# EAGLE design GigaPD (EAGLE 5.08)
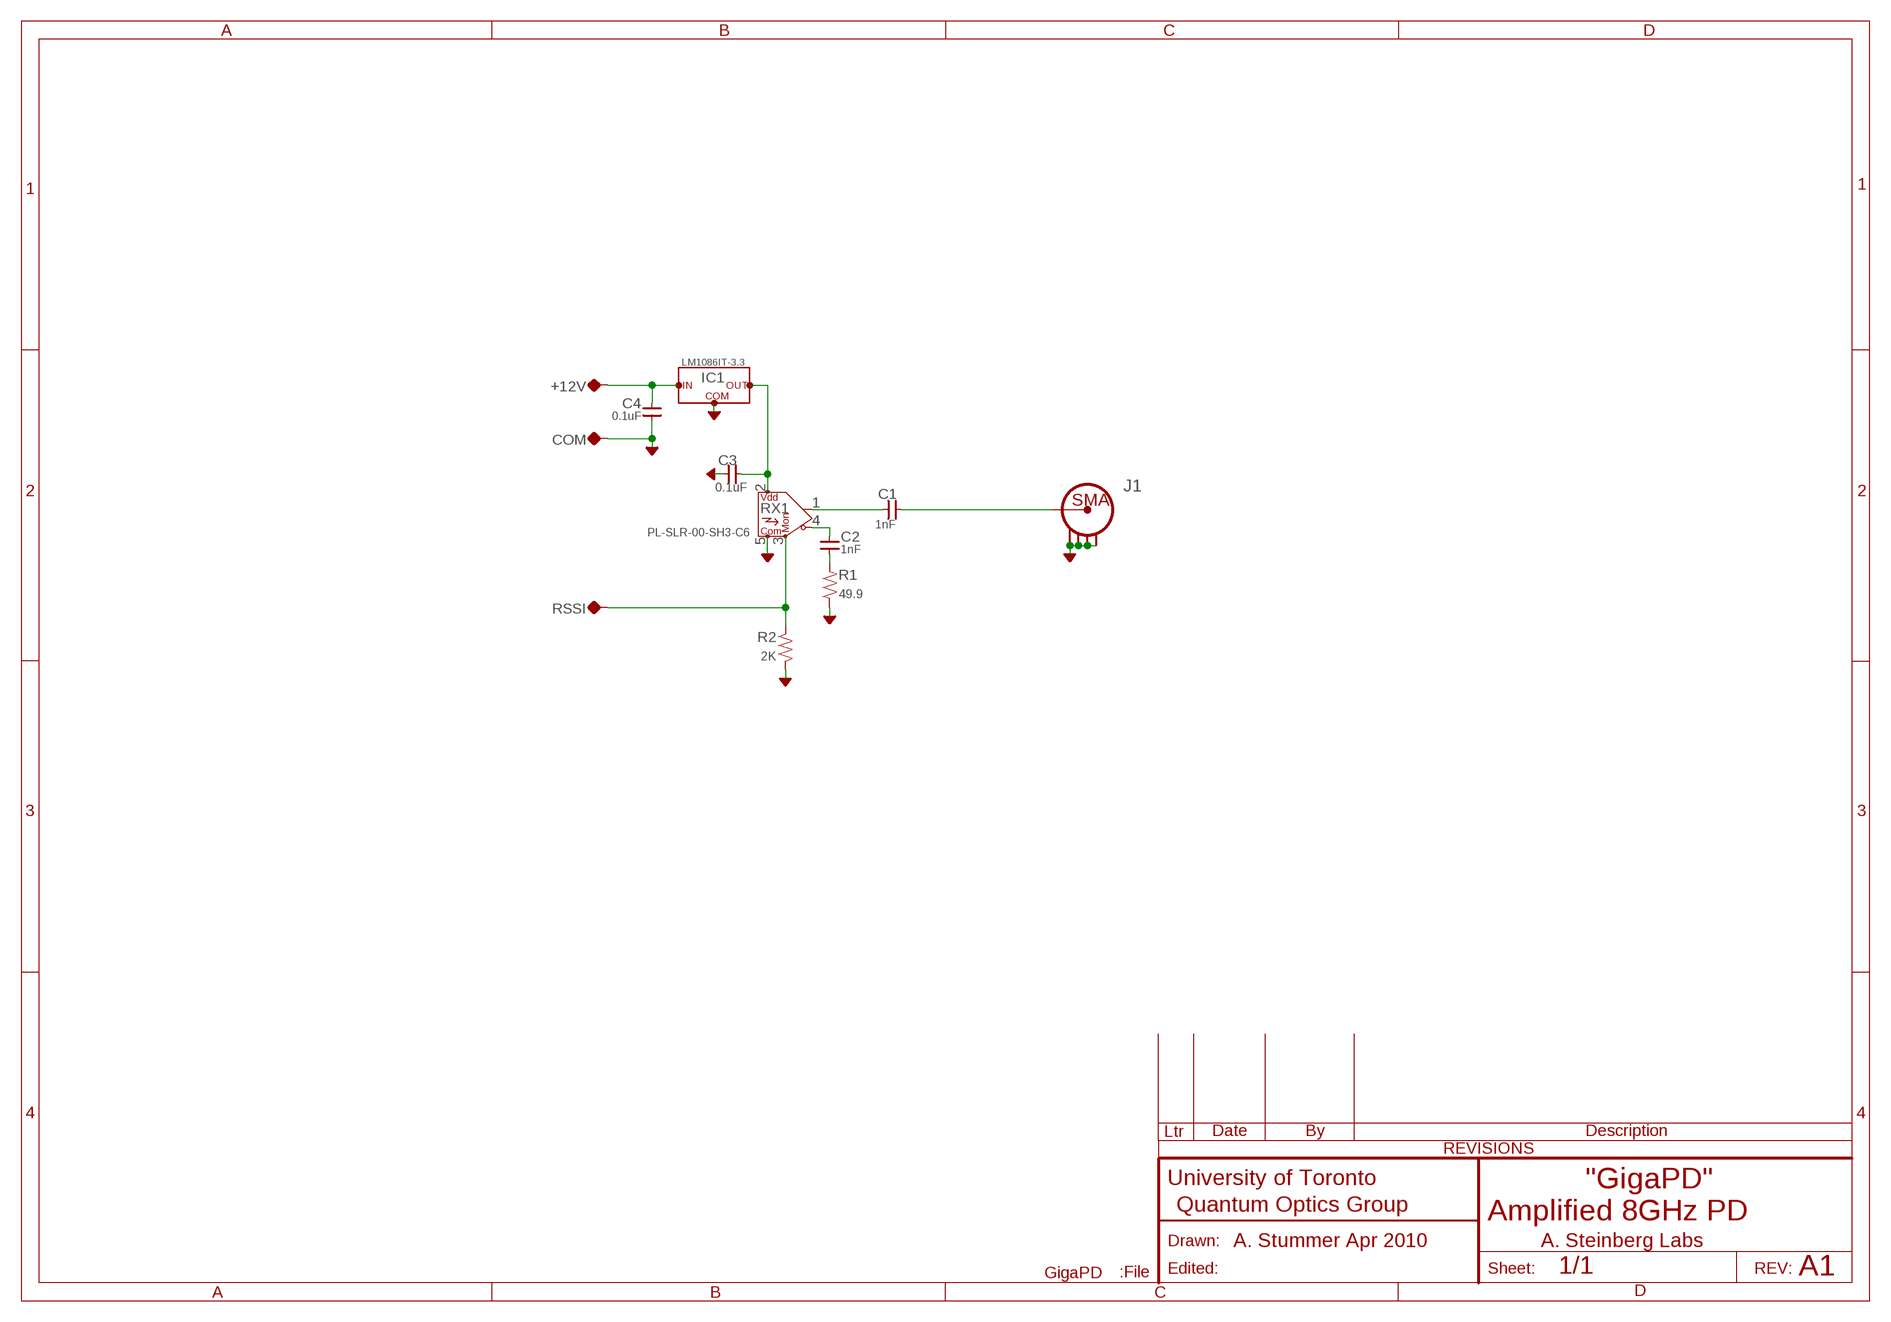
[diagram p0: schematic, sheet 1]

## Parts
+12V  TP-0.042B  [TP-0.042B]
C1  1nF  CAP-H-0402  [1005(0402)]
C2  1nF  CAP-V-0402  [1005(0402)]
C3  0.1uF  CAP-H-0306(REVERSED_GEOMETRY)  [0306(REVERSED_GEOMETRY_0603)]
C4  0.1uF  CAP-V-0402  [1005(0402)]
COM  TP-0.042B  [TP-0.042B]
IC1  LM1086IT-3.3  REGULATOR:LM1086(LDO)-TO220(VERTICAL)  [TO220-VERTICAL]
J1  CONN-SMA  [CONN-SMA1]
R1  49.9  R-V-0402  [1005(0402)]
R2  2K  R-V-0402  [1005(0402)]
RSSI  TP-0.042B  [TP-0.042B]
RX1  PL-SLR-00-SH3-C6  OPTO:PL-SXR-00(JDSU_ROSA)  [OPTO:PL-SXR-00(JDSU_ROSA)]

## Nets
AGND: C3.1 C4.1 COM.TP IC1.1(COM) J1.COM1 J1.COM2 J1.COM3 J1.COM4 R1.1 R2.1 RX1.5(COM)
N$1: R2.2 RSSI.TP RX1.3(RSSI)
N$2: C2.2 RX1.4(OUTN)
N$3: C2.1 R1.2
N$4: C1.1 RX1.1(OUTP)
N$5: C1.2 J1.CONDUCTOR
N$6: C3.2 IC1.2(OUT) RX1.2(VDD)
N$7: +12V.TP C4.2 IC1.3(VI)

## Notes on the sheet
- "GigaPD"
- Amplified 8GHz PD
- A. Stummer Apr 2010 | A. Steinberg Labs
- A1

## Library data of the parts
+12V COM RSSI = QuantumOptics:TP: Testpoint, either SMT pad, small hole or loop style TP such as Keystone 5002K (0.042").
C1 C3 = QuantumOptics:CAP-H-: Cap, SMT and Through-hole, 0402 and up.
C2 C4 = QuantumOptics:CAP-V-: Cap, SMT and Through-hole, 0402 and up.
IC1 = QuantumOptics:REGULATOR:LM1086(LDO): LM1086-xxx, National Semiconductor, LDO, adjustable or fixed. http://cache.national.com/ds/LM/LM1086.pdf
J1 = QuantumOptics:CONN-SMA: SMA PCB Connector.
R1 R2 = QuantumOptics:R-V-*: Resistor, SMT & Through-Hole, vertical symbol
RX1 = QuantumOptics:OPTO:PL-SXR-00(JDSU_ROSA): Optical Receiver, ROSA (Receiver Optical SubAssembly), JDSU such as PL-SxR-00-S43-C6, connectorized, 8.5 or 10Gbps http://www.jdsu.com/product-literature/pl-xxr-00-sh3-c6_ds_cc_ae.pdf

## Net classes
0 default: width 0.178 mm, drill 0.508 mm, clearance 0.178 mm

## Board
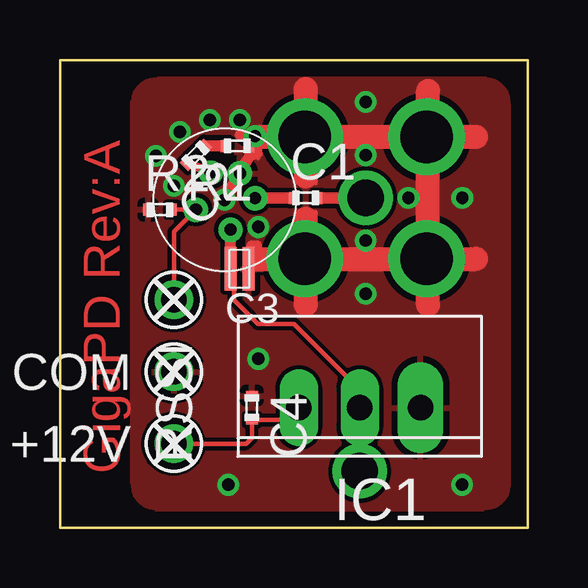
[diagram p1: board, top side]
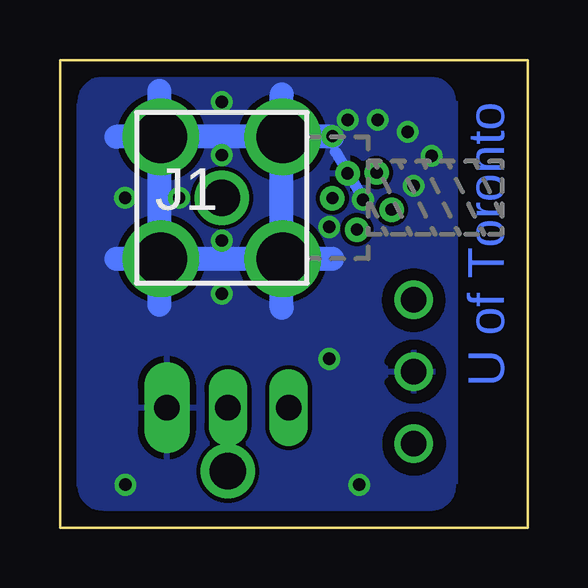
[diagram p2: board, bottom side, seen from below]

Size 19.5 x 19.5 mm. Coordinates in mm from the lower left corner, seen from the top.
Outline: 0,0 19.5,0 19.5,19.5 0,19.5 0,0
Copper layers (1+16): Top 0.035mm / dielectric 1.5mm / Bottom 0.035mm
Design rules "DRC standard check": minimum track width 7mil, minimum drill 20mil, track to track 7mil, track to pad 7mil, pad to pad 7mil, via to via 7mil, smd to smd 0mil, copper to edge 25mil, drill to drill 8mil, minimum pad ring 10mil, minimum via ring 8mil, stop-mask expansion 4mil, vias tented up to drill 0mil, thermal gap 10mil
tRestrict: 11 lines
bRestrict: 6 lines

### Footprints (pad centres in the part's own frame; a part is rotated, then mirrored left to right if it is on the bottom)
TP-0.042B = drill 1.067 round: TP 0,0
1005(0402) = smd 0.4 x 0.5: 1 -0.5,0; 2 0.5,0
0306(REVERSED_GEOMETRY_0603) = smd 0.5 x 1.8: 1 -0.375,0; 2 0.375,0
TO220-VERTICAL = drill 1.067 pad 1.905 long: 1 -2.54,0 | drill 1.067 long: 2 0,0; 3 2.54,0
CONN-SMA1 = drill 2.184 round: COM1 -2.54,-2.54; COM2 -2.54,2.54; COM3 2.54,2.54; COM4 2.54,-2.54 | drill 1.511 round: CONDUCTOR 0,0
OPTO:PL-SXR-00(JDSU_ROSA) = drill 0.508 round: 1 -1.065,-0.692; 2 -0.833,0.959; 3 0.833,0.959; 4 1.065,-0.692; 5 0,-1.27

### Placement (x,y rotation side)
+12V  4.75,3.5 180 top
C1  10.25,13.75 0 top
C2  5.67,15.54 225 top
C3  7.48,10.79 180 top
C4  8,5 270 top
COM  4.75,6.5 180 top
IC1  12.5,5 180 top
J1  12.75,13.75 0 bottom
R1  7.39,15.91 180 top
R2  4.17,13.26 0 top
RSSI  4.75,9.5 270 top
RX1  6.87,13.67 150 top

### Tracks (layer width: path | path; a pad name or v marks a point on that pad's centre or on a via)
AGND  (via drill 0.51)
  Top 0.178: 8.09,16.37 8.01,16.27 R1.1 | 8.37,15.57 8.23,16.27 | 8.37,15.57 8.26,15.41 | 8.37,15.57 8.1,15.7 8.1,15.67 8.02,15.67 8.22,15.72 8.04,15.45 8.04,15.87 | 9.84,14.39 9.84,14.7 10.25,14.7 10.25,14.65 | 10.66,14.68 10.66,14.37 | 9.84,12.83 9.84,13.14 | 10.66,12.85 10.66,13.16 | 8.13,16.12 8.19,15.77 7.89,15.77 R1.1 | 8.23,15.58 8.12,15.42 7.89,15.42 R1.1 | 8.2,11.75 8.2,11.13 C3.1
  Top 0.45: 6.9,13.8 8.02,15.67 | 7.52,16.38 8.09,16.37 | 8.2,11.75 8,11.75
  Top 1: 10.25,9.3 10.25,12.88 | 8.11,11.2 17.35,11.2 | 15.35,9.3 15.35,18.2 | 8.35,16.3 17.35,16.3 | 10.25,14.65 10.25,18.3
  Bottom 0.45: 6.9,13.8 8.02,15.67
  Bottom 1: 8.15,11.2 17.15,11.2 | 8.15,16.3 17.15,16.3 | 15.35,9.3 15.35,18.2 | 10.26,9.16 10.26,18.06
  other vias: 6.25,17 6.87,13.67 5,16.5 4.75,14.25 4,15.5 12.75,15.53 12.75,11.97 14.53,13.75 7.5,17 8.27,12.54 8.27,7.04 8.14,16.32 16.77,1.79 7.02,1.79 16.77,13.75 12.75,17.75 12.75,9.75
  pour Bottom: 3,0 19.5,0 19.5,19.5 3,19.5
  pour Top: 3,0 19.5,0 19.5,19.5 3,19.5
N$1
  Top 0.178: RSSI.TP 4.75,12.34 RX1.3 R2.2
N$2
  Top 0.4: C2.2 RX1.4
N$3
  Top 0.45: C2.1 6.88,15.9 R1.2
N$4
  Top 0.254: RX1.1
  Top 0.4: C1.1 9.65,13.75
  Top 0.48: 9.65,13.75 RX1.1
N$5
  Top 0.4: C1.2 10.85,13.75
  Top 0.48: 10.85,13.75 J1.CONDUCTOR
N$6  (via drill 1.51)
  Top 0.178: 9,8.5 8.25,8.5 7.25,9.5 7.25,10.64 C3.2 | RX1.2 | v12.5,2.35 IC1.2
  Top 0.18: IC1.2 12.5,5.75 9.75,8.5 9,8.5
  Top 0.45: C3.2 RX1.2
N$7
  Top 0.178: +12V.TP 7.75,3.5 8,3.75 C4.2 9.46,4.5 IC1.3

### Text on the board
Top: GigaPD Rev:A
Bottom: U of Toronto
Reference: Sink:577002B04000G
